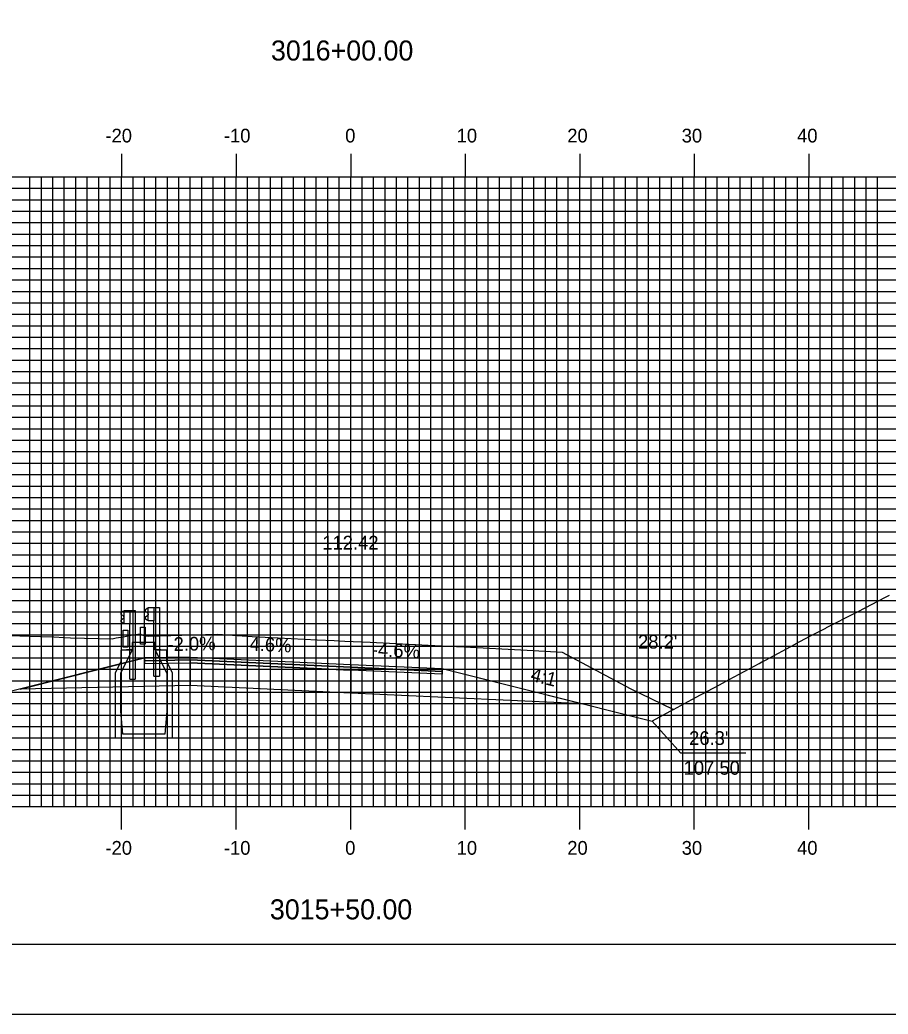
# Model space of a CAD drawing. Extents: x 1685192 to 1685536, y 461260 to 461480.
# Drawn here: x 1685329.3 to 1685405.1, y 461260 to 461346.8 of the extents above; entities that cross this region are included whole.
import ezdxf

# ---------------------------------------------------------------- set-up
doc = ezdxf.new("R2010")
doc.units = 0
for name, color, linetype in [('ANNOTATION', 7, 'Continuous'), ('BORDER', 7, 'Continuous'), ('D_Roadway_Centerline_Text', 7, 'Continuous'), ('D_Roadway_Edge_Shoulder', 7, 'Continuous'), ('D_Roadway_Edge_TW', 7, 'Continuous'), ('D_Roadway_Pavement', 7, 'Continuous'), ('D_Roadway_SlopeLines', 7, 'Continuous'), ('D_Roadway_SubGrade', 7, 'Continuous'), ('D_Text_Standard', 7, 'Continuous'), ('H_V ANNOTATION', 7, 'Continuous'), ('M_Roadway_Centerline', 7, 'Continuous'), ('MAJOR', 7, 'Continuous'), ('MINOR', 7, 'Continuous'), ('PLOT BOUNDARY', 7, 'Continuous'), ('S_Curb_Type_1', 7, 'Continuous'), ('S_Drainage_CB', 7, 'Continuous'), ('S_Guardrail_Beam', 7, 'Continuous'), ('S_Roadway_Centerline', 7, 'Continuous')]:
    doc.layers.add(name, color=color, linetype=linetype)

msp = doc.modelspace()

# ---------------------------------------------------------------- linework, layer by layer
at = {"layer": 'ANNOTATION'}
msp.add_lwpolyline([(1685392.731, 461282.732), (1685387.039, 461282.732), (1685384.539, 461285.55)], dxfattribs=at)
at = {"layer": 'BORDER'}
msp.add_lwpolyline([(1685208.629, 461266.072), (1685528.629, 461266.072), (1685528.629, 461476.072), (1685208.629, 461476.072)], close=True, dxfattribs=at)
at = {"layer": 'D_Roadway_Edge_Shoulder'}
for points in [[(1685344.229, 461291.139), (1685340.229, 461291.059), (1685340.229, 461290.809), (1685344.229, 461290.889)], [(1685344.229, 461290.889), (1685340.229, 461290.809), (1685340.229, 461290.559), (1685344.229, 461290.639)], [(1685358.229, 461290.495), (1685366.229, 461290.127), (1685366.229, 461289.877), (1685358.229, 461290.245)], [(1685358.229, 461290.245), (1685366.229, 461289.877), (1685366.229, 461289.627), (1685358.229, 461289.995)]]:
    msp.add_lwpolyline(points, close=True, dxfattribs=at)
at = {"layer": 'D_Roadway_Edge_TW'}
msp.add_lwpolyline([(1685344.229, 461291.139), (1685358.229, 461290.495), (1685358.229, 461290.245), (1685344.229, 461290.889)], close=True, dxfattribs=at)
at = {"layer": 'D_Roadway_Pavement'}
msp.add_lwpolyline([(1685344.229, 461290.889), (1685358.229, 461290.245), (1685358.229, 461289.995), (1685344.229, 461290.639)], close=True, dxfattribs=at)
for points in [[(1685344.229, 461290.889), (1685344.229, 461290.639)], [(1685344.229, 461290.889), (1685344.229, 461290.639)], [(1685358.229, 461290.245), (1685358.229, 461289.995)], [(1685358.229, 461290.245), (1685358.229, 461289.995)], [(1685358.229, 461290.245), (1685358.229, 461289.995)]]:
    msp.add_lwpolyline(points, dxfattribs=at)
at = {"layer": 'D_Roadway_SlopeLines'}
for p in [(1685366.229, 461290.127), (1685386.419, 461286.561)]:
    msp.add_line(p, (1685384.539, 461285.55), dxfattribs=at)
for points in [[(1685340.229, 461291.059), (1685317.201, 461285.302)], [(1685366.229, 461290.127), (1685384.539, 461285.55)]]:
    msp.add_lwpolyline(points, dxfattribs=at)
at = {"layer": 'D_Roadway_SubGrade'}
for points in [[(1685344.229, 461288.639), (1685329.36, 461288.342), (1685340.229, 461291.059), (1685340.229, 461290.809), (1685344.229, 461290.889), (1685344.229, 461290.639)], [(1685344.229, 461290.639), (1685358.229, 461289.995), (1685358.229, 461287.995), (1685344.229, 461288.639)], [(1685358.229, 461289.995), (1685358.229, 461290.245), (1685366.229, 461289.877), (1685366.229, 461290.127), (1685378.484, 461287.064), (1685358.229, 461287.995)]]:
    msp.add_lwpolyline(points, close=True, dxfattribs=at)
at = {"layer": 'MAJOR'}
for p, q in [((1685338.229, 461335.076), (1685338.229, 461333.072)), ((1685348.229, 461335.076), (1685348.229, 461333.072)), ((1685358.229, 461335.076), (1685358.229, 461333.072)), ((1685368.229, 461335.076), (1685368.229, 461333.072)), ((1685378.229, 461335.076), (1685378.229, 461333.072)), ((1685388.229, 461335.076), (1685388.229, 461333.072)), ((1685398.229, 461335.076), (1685398.229, 461333.072)), ((1685218.229, 461333.072), (1685498.229, 461333.072)), ((1685218.229, 461333.072), (1685498.229, 461333.072)), ((1685338.229, 461278.072), (1685338.229, 461333.072)), ((1685348.229, 461278.072), (1685348.229, 461333.072)), ((1685358.229, 461278.072), (1685358.229, 461333.072)), ((1685368.229, 461278.072), (1685368.229, 461333.072)), ((1685378.229, 461278.072), (1685378.229, 461333.072)), ((1685388.229, 461278.072), (1685388.229, 461333.072)), ((1685398.229, 461278.072), (1685398.229, 461333.072)), ((1685218.229, 461328.072), (1685498.229, 461328.072)), ((1685218.229, 461323.072), (1685498.229, 461323.072)), ((1685218.229, 461318.072), (1685498.229, 461318.072)), ((1685218.229, 461313.072), (1685498.229, 461313.072)), ((1685218.229, 461308.072), (1685498.229, 461308.072)), ((1685218.229, 461303.072), (1685498.229, 461303.072)), ((1685218.229, 461298.072), (1685498.229, 461298.072)), ((1685218.229, 461293.072), (1685498.229, 461293.072)), ((1685218.229, 461288.072), (1685498.229, 461288.072)), ((1685218.229, 461283.072), (1685498.229, 461283.072)), ((1685218.229, 461278.072), (1685498.229, 461278.072)), ((1685218.229, 461278.072), (1685498.229, 461278.072)), ((1685338.229, 461276.068), (1685338.229, 461278.072)), ((1685348.229, 461276.068), (1685348.229, 461278.072)), ((1685358.229, 461276.068), (1685358.229, 461278.072)), ((1685368.229, 461276.068), (1685368.229, 461278.072)), ((1685378.229, 461276.068), (1685378.229, 461278.072)), ((1685388.229, 461276.068), (1685388.229, 461278.072)), ((1685398.229, 461276.068), (1685398.229, 461278.072))]:
    msp.add_line(p, q, dxfattribs=at)
at = {"layer": 'MINOR'}
for p, q in [((1685330.229, 461278.072), (1685330.229, 461333.072)), ((1685331.229, 461278.072), (1685331.229, 461333.072)), ((1685332.229, 461278.072), (1685332.229, 461333.072)), ((1685333.229, 461278.072), (1685333.229, 461333.072)), ((1685334.229, 461278.072), (1685334.229, 461333.072)), ((1685335.229, 461278.072), (1685335.229, 461333.072)), ((1685336.229, 461278.072), (1685336.229, 461333.072)), ((1685337.229, 461278.072), (1685337.229, 461333.072)), ((1685339.229, 461278.072), (1685339.229, 461333.072)), ((1685340.229, 461278.072), (1685340.229, 461333.072)), ((1685341.229, 461278.072), (1685341.229, 461333.072)), ((1685342.229, 461278.072), (1685342.229, 461333.072)), ((1685343.229, 461278.072), (1685343.229, 461333.072)), ((1685344.229, 461278.072), (1685344.229, 461333.072)), ((1685345.229, 461278.072), (1685345.229, 461333.072)), ((1685346.229, 461278.072), (1685346.229, 461333.072)), ((1685347.229, 461278.072), (1685347.229, 461333.072)), ((1685349.229, 461278.072), (1685349.229, 461333.072)), ((1685350.229, 461278.072), (1685350.229, 461333.072)), ((1685351.229, 461278.072), (1685351.229, 461333.072)), ((1685352.229, 461278.072), (1685352.229, 461333.072)), ((1685353.229, 461278.072), (1685353.229, 461333.072)), ((1685354.229, 461278.072), (1685354.229, 461333.072)), ((1685355.229, 461278.072), (1685355.229, 461333.072)), ((1685356.229, 461278.072), (1685356.229, 461333.072)), ((1685357.229, 461278.072), (1685357.229, 461333.072)), ((1685359.229, 461278.072), (1685359.229, 461333.072)), ((1685360.229, 461278.072), (1685360.229, 461333.072)), ((1685361.229, 461278.072), (1685361.229, 461333.072)), ((1685362.229, 461278.072), (1685362.229, 461333.072)), ((1685363.229, 461278.072), (1685363.229, 461333.072)), ((1685364.229, 461278.072), (1685364.229, 461333.072)), ((1685365.229, 461278.072), (1685365.229, 461333.072)), ((1685366.229, 461278.072), (1685366.229, 461333.072)), ((1685367.229, 461278.072), (1685367.229, 461333.072)), ((1685369.229, 461278.072), (1685369.229, 461333.072)), ((1685370.229, 461278.072), (1685370.229, 461333.072)), ((1685371.229, 461278.072), (1685371.229, 461333.072)), ((1685372.229, 461278.072), (1685372.229, 461333.072)), ((1685373.229, 461278.072), (1685373.229, 461333.072)), ((1685374.229, 461278.072), (1685374.229, 461333.072)), ((1685375.229, 461278.072), (1685375.229, 461333.072)), ((1685376.229, 461278.072), (1685376.229, 461333.072)), ((1685377.229, 461278.072), (1685377.229, 461333.072)), ((1685379.229, 461278.072), (1685379.229, 461333.072)), ((1685380.229, 461278.072), (1685380.229, 461333.072)), ((1685381.229, 461278.072), (1685381.229, 461333.072)), ((1685382.229, 461278.072), (1685382.229, 461333.072)), ((1685383.229, 461278.072), (1685383.229, 461333.072)), ((1685384.229, 461278.072), (1685384.229, 461333.072)), ((1685385.229, 461278.072), (1685385.229, 461333.072)), ((1685386.229, 461278.072), (1685386.229, 461333.072)), ((1685387.229, 461278.072), (1685387.229, 461333.072)), ((1685389.229, 461278.072), (1685389.229, 461333.072)), ((1685390.229, 461278.072), (1685390.229, 461333.072)), ((1685391.229, 461278.072), (1685391.229, 461333.072)), ((1685392.229, 461278.072), (1685392.229, 461333.072)), ((1685393.229, 461278.072), (1685393.229, 461333.072)), ((1685394.229, 461278.072), (1685394.229, 461333.072)), ((1685395.229, 461278.072), (1685395.229, 461333.072)), ((1685396.229, 461278.072), (1685396.229, 461333.072)), ((1685397.229, 461278.072), (1685397.229, 461333.072)), ((1685399.229, 461278.072), (1685399.229, 461333.072)), ((1685400.229, 461278.072), (1685400.229, 461333.072)), ((1685401.229, 461278.072), (1685401.229, 461333.072)), ((1685402.229, 461278.072), (1685402.229, 461333.072)), ((1685403.229, 461278.072), (1685403.229, 461333.072)), ((1685404.229, 461278.072), (1685404.229, 461333.072)), ((1685218.229, 461332.072), (1685498.229, 461332.072)), ((1685218.229, 461331.072), (1685498.229, 461331.072)), ((1685218.229, 461330.072), (1685498.229, 461330.072)), ((1685218.229, 461329.072), (1685498.229, 461329.072)), ((1685218.229, 461327.072), (1685498.229, 461327.072)), ((1685218.229, 461326.072), (1685498.229, 461326.072)), ((1685218.229, 461325.072), (1685498.229, 461325.072)), ((1685218.229, 461324.072), (1685498.229, 461324.072)), ((1685218.229, 461322.072), (1685498.229, 461322.072)), ((1685218.229, 461321.072), (1685498.229, 461321.072)), ((1685218.229, 461320.072), (1685498.229, 461320.072)), ((1685218.229, 461319.072), (1685498.229, 461319.072)), ((1685218.229, 461317.072), (1685498.229, 461317.072)), ((1685218.229, 461316.072), (1685498.229, 461316.072)), ((1685218.229, 461315.072), (1685498.229, 461315.072)), ((1685218.229, 461314.072), (1685498.229, 461314.072)), ((1685218.229, 461312.072), (1685498.229, 461312.072)), ((1685218.229, 461311.072), (1685498.229, 461311.072)), ((1685218.229, 461310.072), (1685498.229, 461310.072)), ((1685218.229, 461309.072), (1685498.229, 461309.072)), ((1685218.229, 461307.072), (1685498.229, 461307.072)), ((1685218.229, 461306.072), (1685498.229, 461306.072)), ((1685218.229, 461305.072), (1685498.229, 461305.072)), ((1685218.229, 461304.072), (1685498.229, 461304.072)), ((1685218.229, 461302.072), (1685498.229, 461302.072)), ((1685218.229, 461301.072), (1685498.229, 461301.072)), ((1685218.229, 461300.072), (1685498.229, 461300.072)), ((1685218.229, 461299.072), (1685498.229, 461299.072)), ((1685218.229, 461297.072), (1685498.229, 461297.072)), ((1685218.229, 461296.072), (1685498.229, 461296.072)), ((1685218.229, 461295.072), (1685498.229, 461295.072)), ((1685218.229, 461294.072), (1685498.229, 461294.072)), ((1685218.229, 461292.072), (1685498.229, 461292.072)), ((1685218.229, 461291.072), (1685498.229, 461291.072)), ((1685218.229, 461290.072), (1685498.229, 461290.072)), ((1685218.229, 461289.072), (1685498.229, 461289.072)), ((1685218.229, 461287.072), (1685498.229, 461287.072)), ((1685218.229, 461286.072), (1685498.229, 461286.072)), ((1685218.229, 461285.072), (1685498.229, 461285.072)), ((1685218.229, 461284.072), (1685498.229, 461284.072)), ((1685218.229, 461282.072), (1685498.229, 461282.072)), ((1685218.229, 461281.072), (1685498.229, 461281.072)), ((1685218.229, 461280.072), (1685498.229, 461280.072)), ((1685218.229, 461279.072), (1685498.229, 461279.072))]:
    msp.add_line(p, q, dxfattribs=at)
at = {"layer": 'PLOT BOUNDARY'}
msp.add_lwpolyline([(1685192.443, 461259.954), (1685532.443, 461259.954), (1685532.443, 461479.954), (1685192.443, 461479.954)], close=True, dxfattribs=at)
at = {"layer": 'S_Curb_Type_1'}
for points in [[(1685339.868, 461293.754), (1685340.285, 461293.754), (1685340.285, 461292.254), (1685339.868, 461292.254)], [(1685339.868, 461293.754), (1685340.285, 461293.754), (1685340.285, 461292.254), (1685339.868, 461292.254)], [(1685338.357, 461293.496), (1685338.774, 461293.496), (1685338.774, 461291.996), (1685338.357, 461291.996)], [(1685338.357, 461293.496), (1685338.774, 461293.496), (1685338.774, 461291.996), (1685338.357, 461291.996)]]:
    msp.add_lwpolyline(points, close=True, dxfattribs=at)
at = {"layer": 'S_Drainage_CB'}
for p, q in [((1685339.155, 461291.728), (1685338.171, 461291.728)), ((1685338.171, 461291.728), (1685338.171, 461290.744)), ((1685338.171, 461289.727), (1685339.155, 461291.728)), ((1685342.174, 461291.728), (1685341.157, 461291.728)), ((1685341.157, 461291.728), (1685342.174, 461289.727)), ((1685342.174, 461290.744), (1685342.174, 461291.728)), ((1685338.171, 461290.744), (1685337.679, 461289.727)), ((1685342.666, 461289.727), (1685342.174, 461290.744)), ((1685337.679, 461289.727), (1685337.679, 461284.084)), ((1685338.171, 461286.413), (1685338.171, 461289.727)), ((1685342.174, 461289.727), (1685342.174, 461286.413)), ((1685342.666, 461284.084), (1685342.666, 461289.727)), ((1685338.335, 461284.412), (1685338.171, 461286.413)), ((1685342.174, 461286.413), (1685342.01, 461284.412)), ((1685337.679, 461284.084), (1685342.666, 461284.084)), ((1685342.01, 461284.412), (1685338.335, 461284.412))]:
    msp.add_line(p, q, dxfattribs=at)
msp.add_lwpolyline([(1685341.649, 461291.77), (1685341.157, 461291.77), (1685341.157, 461292.393), (1685339.155, 461292.393), (1685339.155, 461291.77), (1685338.663, 461291.77)], dxfattribs=at)
at = {"layer": 'S_Guardrail_Beam'}
for p, q in [((1685340.456, 461295.364), (1685340.313, 461295.264)), ((1685340.456, 461295.364), (1685340.313, 461295.264)), ((1685340.555, 461295.385), (1685340.473, 461295.371)), ((1685340.555, 461295.385), (1685340.473, 461295.371)), ((1685340.555, 461295.458), (1685341.045, 461295.458)), ((1685340.555, 461294.291), (1685340.555, 461295.458)), ((1685340.555, 461295.458), (1685341.045, 461295.458)), ((1685340.555, 461294.291), (1685340.555, 461295.458)), ((1685341.045, 461295.458), (1685341.536, 461295.458)), ((1685341.045, 461295.458), (1685341.045, 461294.291)), ((1685341.045, 461295.458), (1685341.536, 461295.458)), ((1685341.045, 461295.458), (1685341.045, 461294.291)), ((1685341.536, 461295.458), (1685341.536, 461289.458)), ((1685341.536, 461295.458), (1685341.536, 461289.458)), ((1685338.346, 461295.101), (1685338.203, 461295.001)), ((1685338.346, 461295.101), (1685338.203, 461295.001)), ((1685338.203, 461294.858), (1685338.398, 461294.722)), ((1685338.203, 461294.858), (1685338.398, 461294.722)), ((1685338.398, 461294.502), (1685338.203, 461294.366)), ((1685338.398, 461294.502), (1685338.203, 461294.366)), ((1685338.445, 461295.122), (1685338.363, 461295.108)), ((1685338.445, 461295.122), (1685338.363, 461295.108)), ((1685338.432, 461294.657), (1685338.432, 461294.566)), ((1685338.432, 461294.657), (1685338.432, 461294.566)), ((1685338.445, 461295.195), (1685338.935, 461295.195)), ((1685338.445, 461294.029), (1685338.445, 461295.195)), ((1685338.445, 461295.195), (1685338.935, 461295.195)), ((1685338.445, 461294.029), (1685338.445, 461295.195)), ((1685338.935, 461295.195), (1685339.426, 461295.195)), ((1685338.935, 461295.195), (1685338.935, 461294.029)), ((1685338.935, 461295.195), (1685339.426, 461295.195)), ((1685338.935, 461295.195), (1685338.935, 461294.029)), ((1685339.426, 461295.195), (1685339.426, 461289.195)), ((1685339.426, 461295.195), (1685339.426, 461289.195)), ((1685340.313, 461295.121), (1685340.508, 461294.985)), ((1685340.313, 461295.121), (1685340.508, 461294.985)), ((1685340.508, 461294.765), (1685340.313, 461294.629)), ((1685340.508, 461294.765), (1685340.313, 461294.629)), ((1685340.313, 461294.486), (1685340.456, 461294.386)), ((1685340.313, 461294.486), (1685340.456, 461294.386)), ((1685340.542, 461294.92), (1685340.542, 461294.829)), ((1685340.542, 461294.92), (1685340.542, 461294.829)), ((1685338.203, 461294.223), (1685338.346, 461294.123)), ((1685338.203, 461294.223), (1685338.346, 461294.123)), ((1685338.363, 461294.116), (1685338.445, 461294.101)), ((1685338.363, 461294.116), (1685338.445, 461294.101)), ((1685338.935, 461294.029), (1685338.445, 461294.029)), ((1685338.935, 461294.029), (1685338.445, 461294.029)), ((1685338.935, 461289.195), (1685338.935, 461294.029)), ((1685338.935, 461289.195), (1685338.935, 461294.029)), ((1685340.473, 461294.379), (1685340.555, 461294.364)), ((1685340.473, 461294.379), (1685340.555, 461294.364)), ((1685341.045, 461294.291), (1685340.555, 461294.291)), ((1685341.045, 461294.291), (1685340.555, 461294.291)), ((1685341.045, 461289.458), (1685341.045, 461294.291)), ((1685341.045, 461289.458), (1685341.045, 461294.291)), ((1685338.935, 461289.195), (1685339.426, 461289.195)), ((1685338.935, 461289.195), (1685339.426, 461289.195)), ((1685341.045, 461289.458), (1685341.536, 461289.458)), ((1685341.045, 461289.458), (1685341.536, 461289.458))]:
    msp.add_line(p, q, dxfattribs=at)
for centre, major_axis, start_param, end_param in [((1685340.48, 461295.33), (-0.0417, 0), 4.886922, 5.323254), ((1685340.48, 461295.33), (-0.0417, 0), 4.886922, 5.323254), ((1685338.253, 461294.929), (-0.0877, 0), 5.323254, 7.243116), ((1685338.253, 461294.929), (-0.0877, 0), 5.323254, 7.243116), ((1685338.37, 461295.067), (-0.0417, 0), 4.886922, 5.323254), ((1685338.37, 461295.067), (-0.0417, 0), 4.886922, 5.323254), ((1685338.353, 461294.657), (0.0789, 0), 0, 0.959931), ((1685338.353, 461294.657), (0.0789, 0), 0, 0.959931), ((1685338.353, 461294.566), (0.0789, 0), 5.323254, 6.283185), ((1685338.353, 461294.566), (0.0789, 0), 5.323254, 6.283185), ((1685340.363, 461295.192), (-0.0877, 0), 5.323254, 7.243116), ((1685340.363, 461295.192), (-0.0877, 0), 5.323254, 7.243116), ((1685340.363, 461294.557), (-0.0877, 0), 5.323254, 7.243116), ((1685340.363, 461294.557), (-0.0877, 0), 5.323254, 7.243116), ((1685340.463, 461294.92), (0.0789, 0), 0, 0.959931), ((1685340.463, 461294.92), (0.0789, 0), 0, 0.959931), ((1685340.463, 461294.829), (0.0789, 0), 5.323254, 6.283185), ((1685340.463, 461294.829), (0.0789, 0), 5.323254, 6.283185), ((1685338.253, 461294.294), (-0.0877, 0), 5.323254, 7.243116), ((1685338.253, 461294.294), (-0.0877, 0), 5.323254, 7.243116), ((1685338.37, 461294.157), (-0.0417, 0), 0.959931, 1.396263), ((1685338.37, 461294.157), (-0.0417, 0), 0.959931, 1.396263), ((1685340.48, 461294.42), (-0.0417, 0), 0.959931, 1.396263), ((1685340.48, 461294.42), (-0.0417, 0), 0.959931, 1.396263)]:
    msp.add_ellipse(centre, major_axis=major_axis, ratio=0.995501, start_param=start_param, end_param=end_param, dxfattribs=at)
at = {"layer": 'S_Roadway_Centerline'}
for points in [[(1685376.692, 461291.567), (1685382.636, 461288.378), (1685384.424, 461287.519), (1685386.419, 461286.561), (1685388.341, 461287.594), (1685390.424, 461288.715), (1685391.266, 461289.167), (1685393.901, 461290.584), (1685394.13, 461290.708), (1685394.44, 461290.866), (1685397.022, 461292.26), (1685397.049, 461292.275), (1685397.076, 461292.29), (1685398.307, 461292.954), (1685399.697, 461293.668), (1685399.735, 461293.688), (1685399.774, 461293.708), (1685402.306, 461295.01), (1685402.413, 461295.066), (1685402.526, 461295.124), (1685404.916, 461296.354), (1685405.091, 461296.446), (1685405.275, 461296.541)], [(1685326.604, 461293.088), (1685331.136, 461292.928), (1685332.326, 461292.915), (1685333.225, 461292.843), (1685333.755, 461292.823), (1685337.409, 461292.714), (1685337.764, 461292.803), (1685338.357, 461292.913), (1685339.196, 461293.078), (1685339.868, 461293.171), (1685339.973, 461293.074), (1685340.166, 461293.016), (1685340.567, 461292.967), (1685344.476, 461293.075), (1685346.59, 461293.148), (1685349.627, 461292.939), (1685355.293, 461292.643), (1685356.782, 461292.588), (1685357.731, 461292.532), (1685359.932, 461292.433), (1685366.118, 461292.105), (1685368.136, 461292.037), (1685373.641, 461291.742), (1685376.692, 461291.567)]]:
    msp.add_lwpolyline(points, dxfattribs=at)

# ---------------------------------------------------------------- texts
at = {"layer": 'ANNOTATION'}
for s, rotation, p in [('-2.0%', 1.14576, (1685342.249, 461291.653)), ('4.6%', 357.36625, (1685349.376, 461291.705)), ('-4.6%', 357.36625, (1685360.055, 461291.214)), ('4:1', 345.96376, (1685373.863, 461289.081))]:
    msp.add_text(s, height=1.2, rotation=rotation, dxfattribs=at).set_placement(p)
for s, p in [("26.3' ", (1685387.774, 461283.459)), ('107.50', (1685387.297, 461280.859))]:
    msp.add_text(s, height=1.2, dxfattribs=at).set_placement(p)
at = {"layer": 'D_Roadway_Centerline_Text'}
msp.add_text('112.42', height=1.2, dxfattribs=at).set_placement((1685355.752, 461300.525))
at = {"layer": 'D_Text_Standard'}
msp.add_text("28.2'", height=1.2, dxfattribs=at).set_placement((1685383.315, 461291.873))
at = {"layer": 'H_V ANNOTATION'}
for s, height, p in [('3016+00.00', 1.75, (1685351.269, 461343.228)), ('-20', 1.2, (1685336.816, 461336.072)), ('-10', 1.2, (1685347.159, 461336.072)), ('0', 1.2, (1685357.748, 461336.072)), ('10', 1.2, (1685367.48, 461336.072)), ('20', 1.2, (1685377.137, 461336.072)), ('30', 1.2, (1685387.127, 461336.072)), ('40', 1.2, (1685397.202, 461336.072)), ('-20', 1.2, (1685336.816, 461273.872)), ('-10', 1.2, (1685347.159, 461273.872)), ('0', 1.2, (1685357.748, 461273.872)), ('10', 1.2, (1685367.48, 461273.872)), ('20', 1.2, (1685377.137, 461273.872)), ('30', 1.2, (1685387.127, 461273.872)), ('40', 1.2, (1685397.202, 461273.872)), ('3015+50.00', 1.75, (1685351.175, 461268.228))]:
    msp.add_text(s, height=height, dxfattribs=at).set_placement(p)
at = {"layer": 'M_Roadway_Centerline'}
for s, p in [('C', (1685356.777, 461292.588)), ('L', (1685356.782, 461292.581))]:
    msp.add_text(s, height=0.0146, dxfattribs=at).set_placement(p)

doc.saveas('drawing.dxf')
